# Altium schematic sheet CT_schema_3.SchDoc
size 422 x 246 mm
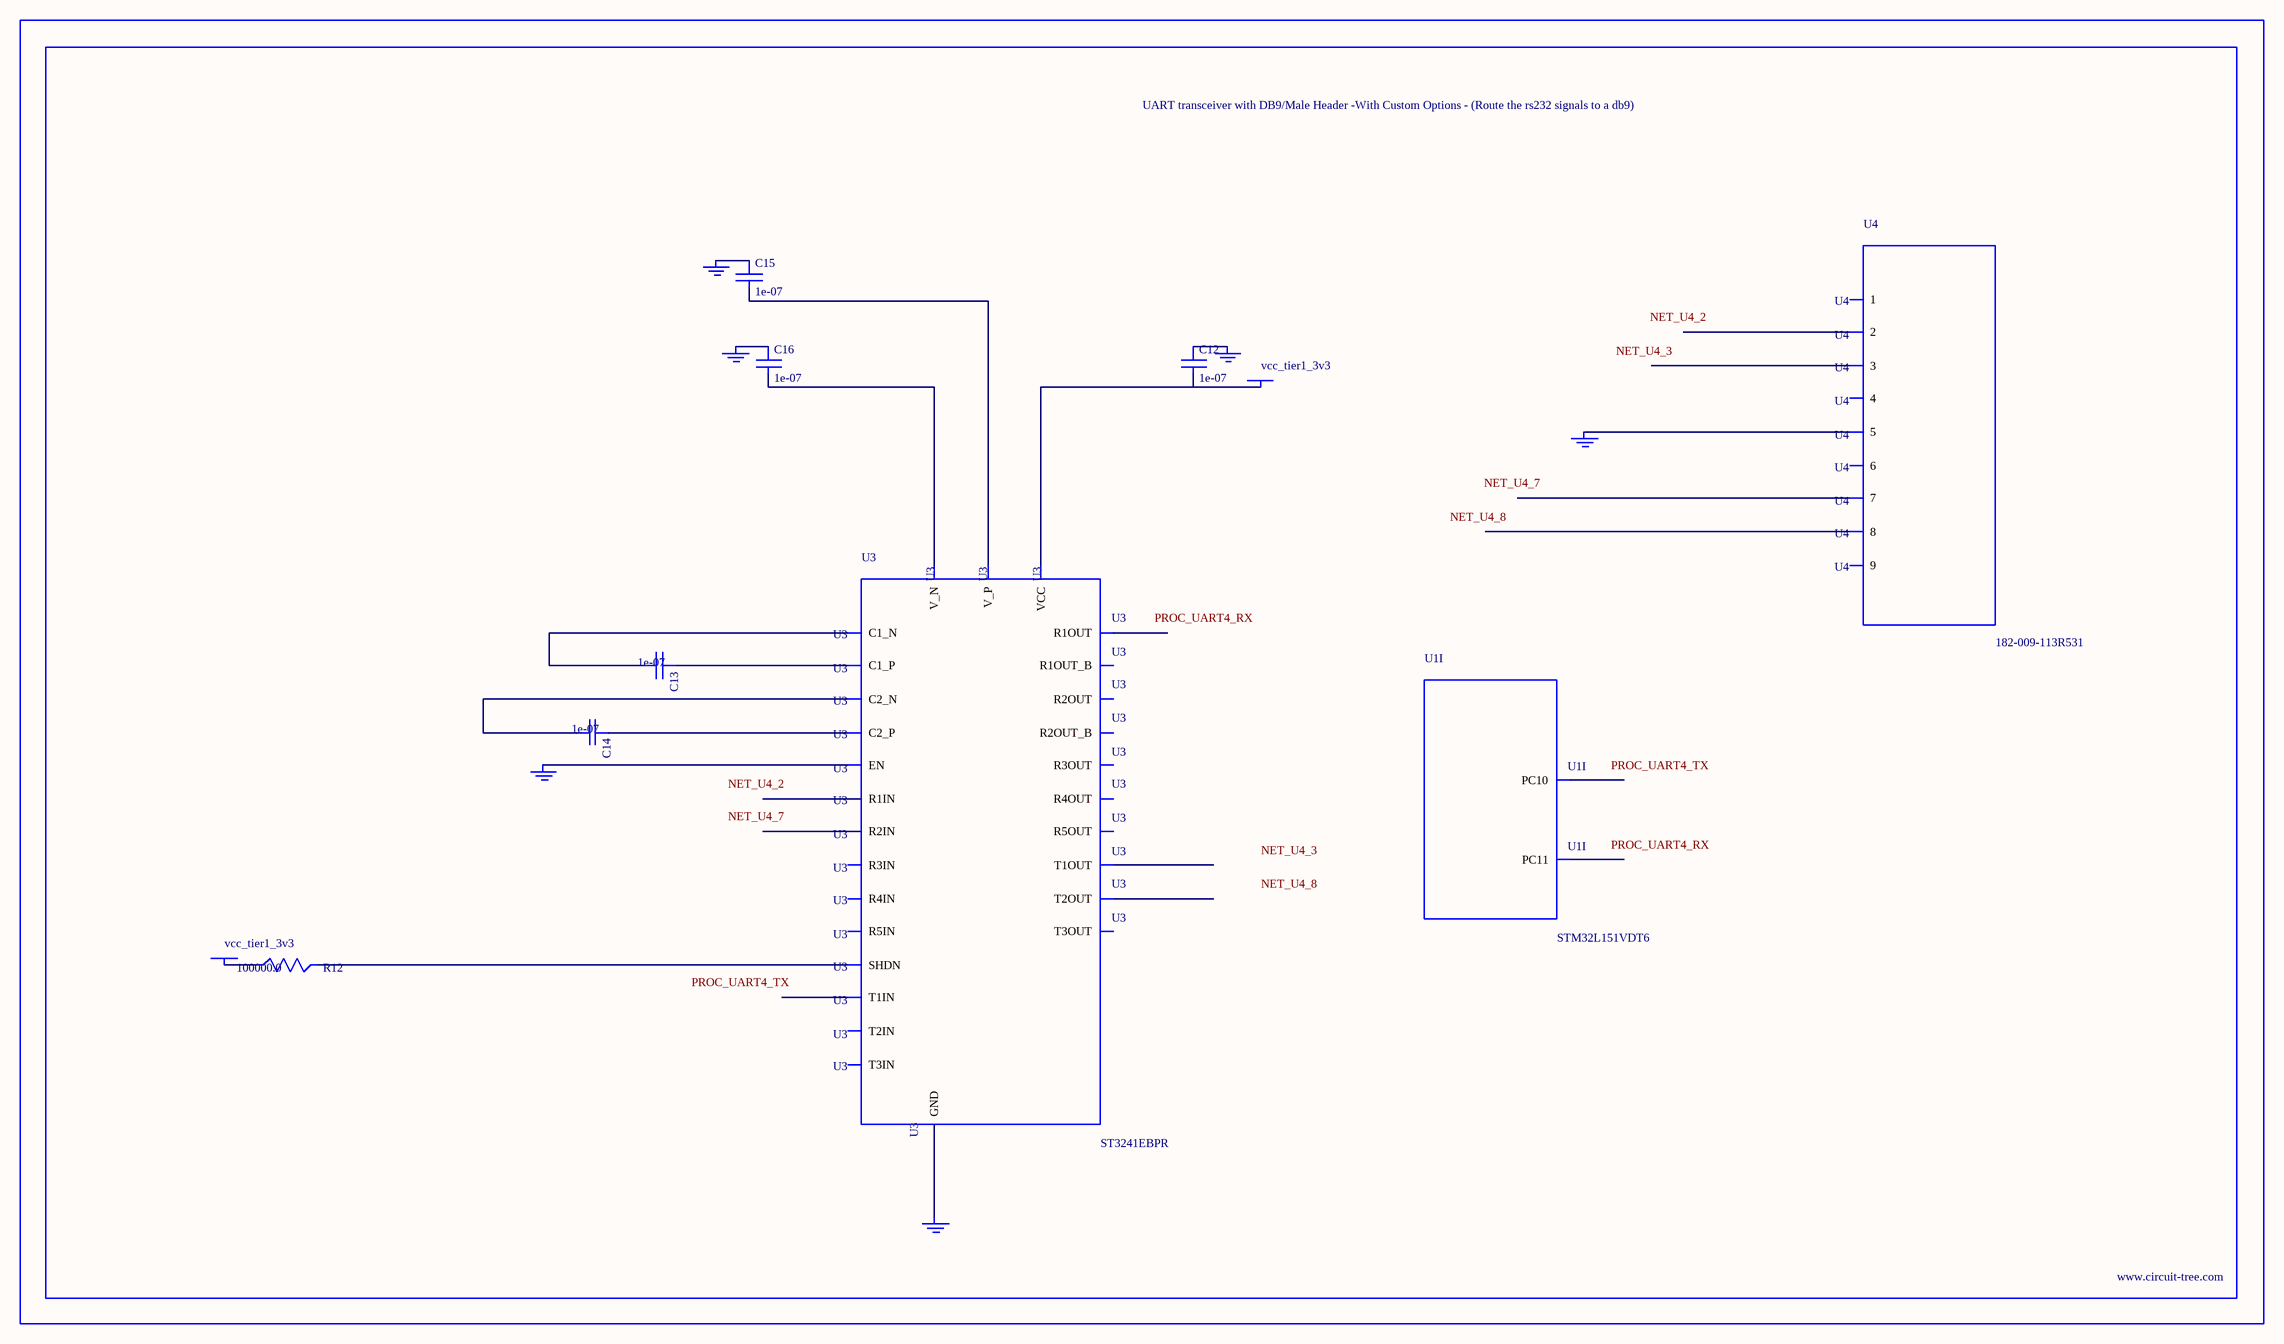
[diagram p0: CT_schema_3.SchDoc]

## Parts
BORDER2  (no value)
C12  1e-07  [C0402]
C13  1e-07  [C0402]
C14  1e-07  [C0402]
C15  1e-07  [C0402]
C16  1e-07  [C0402]
GND_INSTANCE_2_0  (no value)
GND_INSTANCE_2_1  (no value)
GND_INSTANCE_2_2  (no value)
GND_INSTANCE_2_3  (no value)
GND_INSTANCE_2_4  (no value)
GND_INSTANCE_2_5  (no value)
POWER_INSTANCE_2_0  vcc_tier1_3v3
POWER_INSTANCE_2_1  vcc_tier1_3v3
R12  100000.0  [R0603]
U1  STM32L151VDT6  [LQFP100]  (part I of 9)
U3  ST3241EBPR  [SSOP-28]
U4  182-009-113R531  [182-009-MALE]

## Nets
NetC12_1: C12.1 GND_INSTANCE_2_2.0(GND)
NetC12_2: C12.2 POWER_INSTANCE_2_1.0(PWR) U3.26(VCC)
NetC13_1: C13.1 U3.28(C1_P)
NetC13_2: C13.2 U3.24(C1_N)
NetC14_1: C14.1 U3.1(C2_P)
NetC14_2: C14.2 U3.2(C2_N)
NetC15_1: C15.1 GND_INSTANCE_2_3.0(GND)
NetC15_2: C15.2 U3.27(V_P)
NetC16_1: C16.1 GND_INSTANCE_2_0.0(GND)
NetC16_2: C16.2 U3.3(V_N)
NetGND_INSTANCE_2_1_0: GND_INSTANCE_2_1.0(GND) U3.23(EN)
NetGND_INSTANCE_2_4_0: GND_INSTANCE_2_4.0(GND) U3.25(GND)
NetGND_INSTANCE_2_5_0: GND_INSTANCE_2_5.0(GND) U4.5
NetPOWER_INSTANCE_2_0_0: POWER_INSTANCE_2_0.0(PWR) R12.1
NetR12_2: R12.2 U3.22(SHDN)

Not connected (* = marked no-connect by the designer): U1 78(PC10) 79(PC11); U3 4(R1IN) 5(R2IN) 6(R3IN) 7(R4IN) 8(R5IN) 9(T1OUT) 10(T2OUT) 11(T3OUT) 12(T3IN) 13(T2IN) 14(T1IN) 15(R5OUT) 16(R4OUT) 17(R3OUT) 18(R2OUT) 19(R1OUT) 20(R2OUT_B) 21(R1OUT_B); U4 1 2 3 4 6 7 8 9

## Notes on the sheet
- Labels drawn without touching a wire or pin: NET_U4_2, NET_U4_3, NET_U4_7, NET_U4_8, PROC_UART4_RX, PROC_UART4_TX

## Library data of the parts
BORDER2 = BORDER_PAGE2
C12-C16 = C0402C104K3RACTU
GND_INSTANCE_2_0-GND_INSTANCE_2_5 = GND
POWER_INSTANCE_2_0 POWER_INSTANCE_2_1 = PWR
R12 = RC0603JR-07100KL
